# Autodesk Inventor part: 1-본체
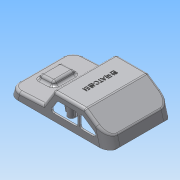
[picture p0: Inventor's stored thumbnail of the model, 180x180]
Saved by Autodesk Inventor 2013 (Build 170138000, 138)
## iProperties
Created: 2015-05
Part Number: 1-본체
Material: ABS 플라스틱
Document SubType Name: Modeling
Designer: Administrator
Density: 7.85 g/cm^3
Mass: 279.283 g
Surface Area: 339.779 cm^2
Volume: 35.5774 cm^3
Author: Administrator
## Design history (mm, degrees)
sketch "스케치1"
  geometry: L1 (-61, -38)-(61, -38); L2 (61, -38)-(61, 38); L3 (61, 38)-(-61, 38); L4 (-61, 38)-(-61, -38); L5 (-61, -38)-(61, 38); L6 (61, -38)-(-61, 38); 1 further point
  constraints: 12 end point, 2 midpoint, 2 parallel, 1 horizontal, 1 perpendicular
  dimensions: "d0" = 122 distance of L2.end L3.end; "d2" = 76 distance of L1.end L2.end
extrude "돌출1" new body sketch "스케치1" distance "d3" = 31; taper "d4" = 0 deg
sketch "스케치2"
  geometry: L1 (0, 0)-(122, 0) reference; L2 (122, 0)-(122, 31) reference; L3 (0, 31)-(122, 31) reference; L4 (0, 0)-(0, 31) reference; L5 (0, 1)-(2.144, 9); L6 (2.144, 9)-(42, 11.089); L7 (92, 31)-(118.833, 12.819); L8 (118.833, 12.819)-(122, 1); L9 (0, 1)-(1, 1); L10 (1, 1)-(1, 0); L11 (122, 1)-(121, 1); L12 (121, 1)-(121, 0); L13 (42, 11.089)-(54.442, 31); L14 (118.833, 12.819)-(122, 11); 1 further point
  constraints: 20 end point, 7 point on line, 4 perpendicular
  dimensions: "d5" = 1 distance of L5.start L9.end; "d7" = 1 distance of L9.end L10.end; "d8" = 105 deg angle of L5 L1; "d9" = 105 deg angle of L8 L1; "d10" = 20 vertical distance of L7.start L14.end; "d11" = 30 horizontal distance of L14.end L7.start; "d12" = 125 deg angle of L13 L6; "d13" = 42 horizontal distance of L6.end L5.start; "d14" = 1 distance of L8.end L11.end; "d15" = 1 distance of L11.end L12.end; "d17" = 9 distance from line of L5.end L1; "d18" = 3 deg angle of L1 L6; "d19" = 60.132 deg angle of L14 L2
extrude "돌출2" sketch "스케치2" distance "d20" = 137.5; taper "d21" = 0 deg
sketch "스케치3"
  geometry: L1 (50, 9.464)-(48.444, 14.553); L2 (48.444, 14.553)-(32.079, 15.41); L3 (32.079, 15.41)-(30, 10.512); L4 (58.856, 9)-(19, 11.089) reference; L5 (61, 1)-(58.856, 9) reference; L6 (60, 0)-(-60, 0) reference; L7 (60, 1)-(61, 1) reference; 2 further points
  constraints: 6 end point, 2 point on line, 1 coincident, 1 parallel
  dimensions: "d25" = 70 deg angle of L3 L4; "d26" = 70 deg angle of L4 L1; "d27" = 11 horizontal distance of point (61, 1) L1.start; "d29" = 20 horizontal distance of L3.end L1.start; "d102" = 5 distance between parallel lines of L2 L4
extrude "돌출3" join sketch "스케치3" stored distance "d30" = 26; taper "d31" = 0 deg
fillet "모깎기1" dims "d32" = 12
fillet "모깎기2" dims "d33" = 3
fillet "모깎기3" dims "d34" = 3
fillet "모깎기4" dims "d35" = 3
feature "쉘1" dims "d36" = 2
sketch "스케치4"
  geometry: L1 (61, 26)-(61, -26) reference; 2 further points
  constraints: 1 horizontal alignment, 1 other
  dimensions: "d37" = 50 distance from line of L1 point (11, 0)
feature "엠보싱1" sketch "스케치4" dims "d0" = 122, "d2" = 76, "d5" = 1, "d7" = 1, "d8" = 105 deg, "d9" = 105 deg, "d10" = 20, "d11" = 30, "d12" = 125 deg, "d13" = 42, "d14" = 1, "d15" = 1, "d17" = 9, "d18" = 3 deg, "d19" = 10.49502, "d38" = 0.5, "d39" = 0
sketch "스케치6"
  geometry: L1 (78.924, 28)-(92.685, 18.676) reference; L2 (43.949, 28)-(78.924, 28) reference; L3 (31.561, 8.175)-(43.949, 28) reference; L4 (45.84, 21.59)-(40.216, 12.59); L5 (42.76, 8)-(68.348, 8); L6 (71.348, 11)-(71.348, 20); L7 (68.348, 23)-(48.384, 23); L8 (73.528, 20)-(73.528, 11); L9 (76.528, 8)-(89.752, 8); L10 (76.528, 23)-(77.39, 23); L11 (77.39, 23)-(91.435, 13.484); A1 r 3 centre (42.76, 11) between (40.216, 12.59) and (42.76, 8); A2 r 3 centre (48.384, 20) between (48.384, 23) and (45.84, 21.59); A3 r 3 centre (68.348, 20) between (71.348, 20) and (68.348, 23); A4 r 3 centre (68.348, 11) between (68.348, 8) and (71.348, 11); A5 r 3 centre (89.752, 11) between (89.752, 8) and (91.435, 13.484); A6 r 3 centre (76.528, 11) between (73.528, 11) and (76.528, 8); A7 r 3 centre (76.528, 20) between (76.528, 23) and (73.528, 20); 7 further points
  constraints: 16 end point, 14 point on circle, 14 tangent, 12 point on line, 7 centre point, 5 equal radius, 4 parallel, 4 perpendicular
  dimensions: "d88" = 15 distance of point (71.348, 8) point (71.348, 23); "d90" = 34 distance of point (37.348, 8) point (71.348, 8); "d91" = 5 distance between parallel lines of L3 L4; "d92" = 5 distance between parallel lines of L2 L7; "d93" = 3 radius of A1; "d95" = 26 distance of point (73.528, 8) point (99.528, 8); "d96" = 15 distance of point (73.528, 23) point (73.528, 8); "d97" = 5 distance between parallel lines of L1 L11; "d98" = 5 distance between parallel lines of L2 L10; "d99" = 3 radius of A5
extrude "돌출5" cut sketch "스케치6" stored distance "d100" = 26; taper "d101" = 0 deg
node "작업 평면1"
node "작업 평면2"
sketch "스케치7"
  geometry: A1 r 4 centre (0, 46) between (0, 42) and (0, 50); A2 r 4 centre (0, 35) between (0, 31) and (0, 39); A3 r 4 centre (0, 15) between (0, 11) and (0, 19); A4 r 4 centre (0, 4) between (0, 0) and (0, 8); 2 further points
  constraints: 8 point on circle, 4 centre point, 3 equal radius, 12 other
  dimensions: "d103" = 8 diameter of A1; "d105" = 11 distance of A2.centre A1.centre; "d106" = 20 distance of A3.centre A2.centre; "d107" = 11 distance of A4.centre A3.centre
extrude "돌출6" join sketch "스케치7" distance "d108" = 2; taper "d109" = 0 deg
fillet "모깎기5" dims "d110" = 1
sketch "스케치5"
  geometry: L1 (-60, -31.281)-(-60, 31.281) reference; L2 (60, 31.281)-(60, -31.281) reference; C1 r 4 at (-5, 22); C2 r 4 at (-39, -22); C3 r 4 at (1, -22); C4 r 4 at (39, 0); 1 further point
  constraints: 4 centre point, 3 equal radius, 2 horizontal alignment
  dimensions: "d40" = 4 radius of C1; "d45" = 22 vertical distance of C1.centre point (0, 0); "d47" = 22 vertical distance of point (0, 0) C2.centre; "d48" = 40 distance of C3.centre C2.centre; "d49" = 21 distance from line of C2.centre L1; "d112" = 44 horizontal distance of C4.centre C1.centre; "d113" = 21 distance from line of C4.centre L2
extrude "돌출4" join sketch "스케치5" stored distance "d50" = 26; taper "d51" = 0 deg
hole "구멍1" diameter "d54" = 3.242; stored, may be unused: countersink angle "d58" = 90 deg, drill point angle "d60" = 118 deg; dims "d52" = 10, "d53" = 10, "d55" = 9, "d56" = 4, "d57" = 2, "d59" = 11
hole "구멍2" diameter "d63" = 3.242; stored, may be unused: countersink angle "d67" = 90 deg, drill point angle "d69" = 118 deg; dims "d61" = 10, "d62" = 10, "d64" = 9, "d65" = 4, "d66" = 2, "d68" = 11
hole "구멍3" diameter "d72" = 3.242; stored, may be unused: countersink angle "d76" = 90 deg, drill point angle "d78" = 118 deg; dims "d70" = 10, "d71" = 10, "d73" = 9, "d74" = 4, "d75" = 2, "d77" = 11
hole "구멍4" diameter "d81" = 3.242; stored, may be unused: countersink angle "d85" = 90 deg, drill point angle "d87" = 118 deg; dims "d82" = 9, "d83" = 4, "d84" = 2, "d86" = 11, "d114" = 10, "d115" = 10
node "작업 평면3"
sketch "스케치10"
  geometry: L1 (4, 1)-(6, 1); L2 (6, 1)-(6, -1); L3 (6, -1)-(4, -1); L4 (4, -1)-(4, 1); L5 (4, 1)-(6, -1); L6 (6, 1)-(4, -1); C1 r 4 at (0, 0) reference; 3 further points
  constraints: 12 end point, 3 midpoint, 2 parallel, 1 horizontal, 1 horizontal alignment, 1 perpendicular, 1 tangent
  dimensions: "d122" = 2 distance of L1.start L1.end; "d124" = 2 distance of L1.end L2.end
extrude "돌출8" join sketch "스케치10" stored distance "d125" = 2; taper "d126" = 5 deg
sketch "스케치11"
  geometry: L1 (-6, 1)-(-4, 1); L2 (-4, 1)-(-4, -1); L3 (-4, -1)-(-6, -1); L4 (-6, -1)-(-6, 1); L5 (-6, 1)-(-4, -1); L6 (-4, 1)-(-6, -1); L7 (-40, -43)-(-38, -43); L8 (-38, -43)-(-38, -45); L9 (-38, -45)-(-40, -45); L10 (-40, -45)-(-40, -43); L11 (-40, -43)-(-38, -45); L12 (-38, -43)-(-40, -45); L13 (-30, -45)-(-28, -45); L14 (-28, -45)-(-28, -43); L15 (-28, -43)-(-30, -43); L16 (-30, -43)-(-30, -45); L17 (-30, -45)-(-28, -43); L18 (-28, -45)-(-30, -43); L19 (0, -43)-(2, -43); L20 (2, -43)-(2, -45); L21 (2, -45)-(0, -45); L22 (0, -45)-(0, -43); L23 (0, -43)-(2, -45); L24 (2, -43)-(0, -45); L25 (10, -43)-(12, -43); L26 (12, -43)-(12, -45); L27 (12, -45)-(10, -45); L28 (10, -45)-(10, -43); L29 (10, -43)-(12, -45); L30 (12, -43)-(10, -45); L31 (38, -21)-(40, -21); L32 (40, -21)-(40, -23); L33 (40, -23)-(38, -23); L34 (38, -23)-(38, -21); L35 (38, -21)-(40, -23); L36 (40, -21)-(38, -23); L37 (48, -21)-(50, -21); L38 (50, -21)-(50, -23); L39 (50, -23)-(48, -23); L40 (48, -23)-(48, -21); L41 (48, -21)-(50, -23); L42 (50, -21)-(48, -23); C1 r 4 at (6, -44) reference; C2 r 4 at (-34, -44) reference; C3 r 4 at (0, 0) reference; C4 r 4 at (44, -22) reference; 15 further points
  constraints: 84 end point, 21 midpoint, 14 parallel, 14 perpendicular, 7 horizontal, 7 horizontal alignment, 7 tangent
  dimensions: "d127" = 2 distance of L1.start L1.end; "d129" = 2 distance of L7.start L7.end; "d130" = 2 distance of L14.end L15.end; "d131" = 2 distance of L19.start L19.end; "d132" = 2 distance of L25.start L25.end; "d133" = 2 distance of L31.start L31.end; "d134" = 2 distance of L37.start L37.end
extrude "돌출9" join sketch "스케치11" stored distance "d135" = 2; taper "d136" = 5 deg
node "솔리드1"
other parameters: "d121" = -2
